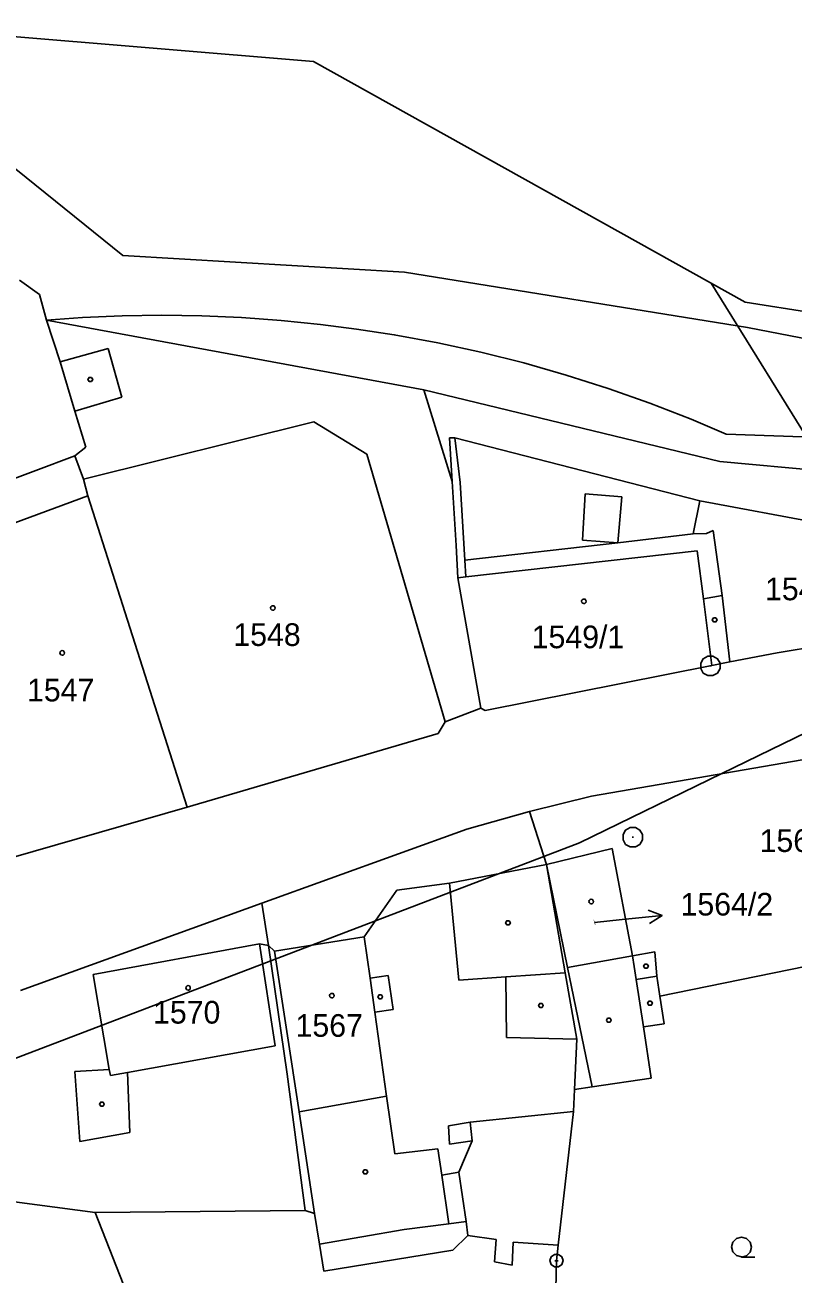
# Model space of a CAD drawing. Extents: x -806774 to -803680, y -1151731 to -1150053.
# Drawn here: x -805628.6 to -805571, y -1150573.9 to -1150480.1 of the extents above; entities that cross this region are included whole.
import ezdxf

# ---------------------------------------------------------------- set-up
doc = ezdxf.new("R2010")
doc.units = 0
for name, color, linetype in [('1', 7, 'Continuous'), ('11', 7, 'Continuous'), ('12', 7, 'Continuous'), ('2', 7, 'Continuous'), ('3', 7, 'Continuous'), ('4', 7, 'Continuous'), ('5', 7, 'Continuous'), ('6', 7, 'Continuous'), ('7', 7, 'Continuous'), ('8', 7, 'Continuous')]:
    doc.layers.add(name, color=color, linetype=linetype)

msp = doc.modelspace()

# ---------------------------------------------------------------- linework, layer by layer
at = {"layer": '1'}
for p, q in [((-805606.97, -1150482.85), (-805639.91, -1150480.12)), ((-805606.97, -1150482.85), (-805582.6, -1150496.44)), ((-805582.6, -1150496.44), (-805574.56, -1150500.92)), ((-805629.05, -1150499.28), (-805627.54, -1150500.35)), ((-805627.54, -1150500.35), (-805627.02, -1150502.26)), ((-805574.56, -1150500.92), (-805569.48, -1150501.72)), ((-805627.02, -1150502.26), (-805626, -1150505.41)), ((-805627.02, -1150502.26), (-805598.69, -1150507.5)), ((-805626, -1150505.41), (-805622.4, -1150504.41)), ((-805621.36, -1150508.04), (-805622.4, -1150504.41)), ((-805624.88, -1150509.11), (-805621.36, -1150508.04)), ((-805598.69, -1150507.5), (-805596.55, -1150514.37)), ((-805576.47, -1150512.87), (-805598.69, -1150507.5)), ((-805624.88, -1150509.11), (-805624.07, -1150511.8)), ((-805624.07, -1150511.8), (-805624.88, -1150512.45)), ((-805596.35, -1150511.09), (-805596.75, -1150511.11)), ((-805596.75, -1150511.11), (-805596.55, -1150514.37)), ((-805577.98, -1150515.83), (-805596.35, -1150511.09)), ((-805624.88, -1150512.45), (-805624.23, -1150514.21)), ((-805545.02, -1150515.82), (-805576.47, -1150512.87)), ((-805623.92, -1150515.45), (-805624.23, -1150514.21)), ((-805596.55, -1150514.37), (-805596.25, -1150519.18)), ((-805623.92, -1150515.45), (-805616.46, -1150538.83)), ((-805577.98, -1150515.83), (-805578.46, -1150518.31)), ((-805561.26, -1150518.96), (-805577.98, -1150515.83)), ((-805578.46, -1150518.31), (-805577.47, -1150518.27)), ((-805577.47, -1150518.27), (-805576.96, -1150518.06)), ((-805576.96, -1150518.06), (-805576.3, -1150522.94)), ((-805596.25, -1150519.18), (-805596.13, -1150521.6)), ((-805596.13, -1150521.6), (-805594.41, -1150531.4)), ((-805576.3, -1150522.94), (-805575.71, -1150527.92)), ((-805560.9, -1150525.36), (-805572.16, -1150527.23)), ((-805572.16, -1150527.23), (-805575.71, -1150527.92)), ((-805594.09, -1150531.56), (-805577.06, -1150528.18)), ((-805575.71, -1150527.92), (-805577.06, -1150528.18)), ((-805597.08, -1150532.42), (-805594.41, -1150531.4)), ((-805594.41, -1150531.4), (-805594.09, -1150531.56)), ((-805597.08, -1150532.42), (-805597.62, -1150533.3)), ((-805597.62, -1150533.3), (-805616.46, -1150538.83)), ((-805567, -1150534.69), (-805586.09, -1150537.99)), ((-805586.09, -1150537.99), (-805590.75, -1150539.15)), ((-805616.46, -1150538.83), (-805629.68, -1150542.61)), ((-805590.75, -1150539.15), (-805595.46, -1150540.47)), ((-805589.49, -1150543.12), (-805590.75, -1150539.15)), ((-805595.46, -1150540.47), (-805610.86, -1150546.01)), ((-805584.56, -1150541.93), (-805589.49, -1150543.12)), ((-805583.02, -1150549.97), (-805584.56, -1150541.93)), ((-805589.49, -1150543.12), (-805588.08, -1150551.24)), ((-805610.86, -1150546.01), (-805628.96, -1150552.57)), ((-805610.34, -1150549.2), (-805610.86, -1150546.01)), ((-805608.95, -1150558.85), (-805610.34, -1150549.2)), ((-805559.52, -1150548.6), (-805580.96, -1150553)), ((-805581.35, -1150549.67), (-805583.02, -1150549.97)), ((-805581.2, -1150551.5), (-805581.35, -1150549.67)), ((-805588.08, -1150551.24), (-805587.21, -1150556.23)), ((-805580.96, -1150553), (-805581.2, -1150551.5)), ((-805580.65, -1150555.07), (-805580.96, -1150553)), ((-805582.2, -1150555.31), (-805580.65, -1150555.07)), ((-805581.62, -1150559.15), (-805582.2, -1150555.31)), ((-805587.21, -1150556.23), (-805587.39, -1150560.01)), ((-805607.59, -1150569.08), (-805608.95, -1150558.85)), ((-805586.06, -1150559.81), (-805581.62, -1150559.15)), ((-805587.39, -1150560.01), (-805587.46, -1150561.66)), ((-805587.39, -1150560.01), (-805586.06, -1150559.81)), ((-805587.46, -1150561.66), (-805588.6, -1150571.69)), ((-805638.87, -1150567.2), (-805623.37, -1150569.23)), ((-805623.37, -1150569.23), (-805607.59, -1150569.08)), ((-805623.37, -1150569.23), (-805618.69, -1150581.09)), ((-805606.9, -1150569.31), (-805607.59, -1150569.08)), ((-805606.51, -1150571.62), (-805606.9, -1150569.31)), ((-805606.2, -1150573.64), (-805606.51, -1150571.62)), ((-805595.38, -1150570.95), (-805596.52, -1150572.06)), ((-805593.25, -1150571.25), (-805595.38, -1150570.95)), ((-805593.39, -1150572.95), (-805593.25, -1150571.25)), ((-805591.98, -1150571.46), (-805592.07, -1150573.19)), ((-805591.98, -1150571.46), (-805588.6, -1150571.69)), ((-805588.6, -1150571.69), (-805588.73, -1150572.86)), ((-805596.52, -1150572.06), (-805606.2, -1150573.64)), ((-805592.07, -1150573.19), (-805593.39, -1150572.95)), ((-805589.35, -1150595.34), (-805588.73, -1150572.86))]:
    msp.add_line(p, q, dxfattribs=at)
at = {"layer": '11'}
msp.add_lwpolyline([(-805774, -1150600.5), (-805744.72, -1150597.99), (-805739, -1150597.5), (-805729.96, -1150594.42), (-805690.5, -1150581), (-805687.13, -1150579.72), (-805686.21, -1150579.36), (-805662.62, -1150570.36), (-805635.57, -1150560.04), (-805633.48, -1150559.24), (-805610.18, -1150550.34), (-805589.68, -1150542.52), (-805587, -1150541.5), (-805576.31, -1150536.3), (-805549.76, -1150523.38), (-805549.38, -1150523.2), (-805535.32, -1150516.36), (-805514.906, -1150506.423)], dxfattribs=at)
at = {"layer": '12'}
for p, q in [((-805624.23, -1150514.21), (-805606.95, -1150509.89)), ((-805606.95, -1150509.89), (-805602.98, -1150512.33)), ((-805602.98, -1150512.33), (-805597.08, -1150532.42)), ((-805623.92, -1150515.45), (-805624.23, -1150514.21)), ((-805636.35, -1150520.07), (-805623.92, -1150515.45)), ((-805623.92, -1150515.45), (-805616.46, -1150538.83)), ((-805623.92, -1150515.45), (-805616.46, -1150538.83)), ((-805578.16, -1150519.57), (-805595.53, -1150521.53)), ((-805577.7, -1150523.19), (-805578.16, -1150519.57)), ((-805595.53, -1150521.53), (-805596.13, -1150521.6)), ((-805596.13, -1150521.6), (-805594.41, -1150531.4)), ((-805577.7, -1150523.19), (-805577.06, -1150528.18)), ((-805594.09, -1150531.56), (-805577.06, -1150528.18)), ((-805594.41, -1150531.4), (-805594.09, -1150531.56)), ((-805597.08, -1150532.42), (-805597.62, -1150533.3)), ((-805597.62, -1150533.3), (-805616.46, -1150538.83)), ((-805616.46, -1150538.83), (-805629.68, -1150542.61)), ((-805584.56, -1150541.93), (-805589.49, -1150543.12)), ((-805583.02, -1150549.97), (-805584.56, -1150541.93)), ((-805587.9, -1150550.85), (-805589.49, -1150543.12)), ((-805623.52, -1150551.37), (-805611.02, -1150549.07)), ((-805611.02, -1150549.07), (-805609.84, -1150556.74)), ((-805609.91, -1150549.62), (-805603.17, -1150548.54)), ((-805602.73, -1150551.65), (-805603.17, -1150548.54)), ((-805608.04, -1150561.69), (-805609.91, -1150549.62)), ((-805587.9, -1150550.85), (-805583.02, -1150549.97)), ((-805622.32, -1150558.5), (-805623.52, -1150551.37)), ((-805602.37, -1150554.2), (-805602.73, -1150551.65)), ((-805602.37, -1150554.2), (-805601.48, -1150560.51)), ((-805609.84, -1150556.74), (-805620.94, -1150558.73)), ((-805622.21, -1150558.95), (-805622.32, -1150558.5)), ((-805620.94, -1150558.73), (-805622.21, -1150558.95)), ((-805601.48, -1150560.51), (-805608.04, -1150561.69))]:
    msp.add_line(p, q, dxfattribs=at)
at = {"layer": '3'}
msp.add_lwpolyline([(-805574.83, -1150572.56), (-805575.21, -1150572.46), (-805575.48, -1150572.19), (-805575.58, -1150571.82), (-805575.48, -1150571.45), (-805575.21, -1150571.18), (-805574.84, -1150571.08), (-805574.47, -1150571.18), (-805574.2, -1150571.45), (-805574.1, -1150571.83), (-805574.2, -1150572.21), (-805574.47, -1150572.48), (-805574.85, -1150572.58), (-805573.85, -1150572.58)], dxfattribs=at)
at = {"layer": '4'}
for p, q in [((-805621.28, -1150497.43), (-805641.35, -1150481.25)), ((-805600.14, -1150498.68), (-805621.28, -1150497.43)), ((-805600.14, -1150498.68), (-805574.4, -1150502.81)), ((-805574.4, -1150502.81), (-805547.02, -1150508.22)), ((-805626, -1150505.41), (-805624.88, -1150509.11)), ((-805624.23, -1150514.21), (-805606.95, -1150509.89)), ((-805606.95, -1150509.89), (-805602.98, -1150512.33)), ((-805545.68, -1150511.92), (-805575.98, -1150510.83)), ((-805596.35, -1150511.09), (-805595.96, -1150514.45)), ((-805637.24, -1150517.09), (-805624.88, -1150512.45)), ((-805602.98, -1150512.33), (-805597.08, -1150532.42)), ((-805595.96, -1150514.45), (-805595.61, -1150520.29)), ((-805636.35, -1150520.07), (-805623.92, -1150515.45)), ((-805586.78, -1150518.78), (-805586.57, -1150515.31)), ((-805586.57, -1150515.31), (-805583.83, -1150515.54)), ((-805583.83, -1150515.54), (-805584.13, -1150518.98)), ((-805584.13, -1150518.98), (-805578.46, -1150518.31)), ((-805595.61, -1150520.29), (-805584.13, -1150518.98)), ((-805584.13, -1150518.98), (-805586.78, -1150518.78)), ((-805595.61, -1150520.29), (-805595.53, -1150521.53)), ((-805578.16, -1150519.57), (-805595.53, -1150521.53)), ((-805577.7, -1150523.19), (-805578.16, -1150519.57)), ((-805595.53, -1150521.53), (-805596.13, -1150521.6)), ((-805576.3, -1150522.94), (-805577.7, -1150523.19)), ((-805577.7, -1150523.19), (-805577.06, -1150528.18)), ((-805596.77, -1150544.52), (-805589.49, -1150543.12)), ((-805587.9, -1150550.85), (-805589.49, -1150543.12)), ((-805600.71, -1150545.04), (-805596.77, -1150544.52)), ((-805596.77, -1150544.52), (-805596.06, -1150551.79)), ((-805603.17, -1150548.54), (-805600.71, -1150545.04)), ((-805623.52, -1150551.37), (-805611.02, -1150549.07)), ((-805611.02, -1150549.07), (-805610.34, -1150549.2)), ((-805611.02, -1150549.07), (-805609.84, -1150556.74)), ((-805610.34, -1150549.2), (-805609.91, -1150549.62)), ((-805609.91, -1150549.62), (-805603.17, -1150548.54)), ((-805602.73, -1150551.65), (-805603.17, -1150548.54)), ((-805608.04, -1150561.69), (-805609.91, -1150549.62)), ((-805587.9, -1150550.85), (-805583.02, -1150549.97)), ((-805583.02, -1150549.97), (-805582.9, -1150550.78)), ((-805588.08, -1150551.24), (-805592.53, -1150551.55)), ((-805586.06, -1150559.81), (-805587.9, -1150550.85)), ((-805582.9, -1150550.78), (-805582.75, -1150551.75)), ((-805622.32, -1150558.5), (-805623.52, -1150551.37)), ((-805602.73, -1150551.65), (-805601.36, -1150551.44)), ((-805602.37, -1150554.2), (-805602.73, -1150551.65)), ((-805601.36, -1150551.44), (-805601, -1150554.01)), ((-805596.06, -1150551.79), (-805592.53, -1150551.55)), ((-805592.53, -1150551.55), (-805592.48, -1150556.11)), ((-805582.75, -1150551.75), (-805581.2, -1150551.5)), ((-805582.75, -1150551.75), (-805582.2, -1150555.31)), ((-805601, -1150554.01), (-805602.37, -1150554.2)), ((-805602.37, -1150554.2), (-805601.48, -1150560.51)), ((-805609.84, -1150556.74), (-805620.94, -1150558.73)), ((-805592.48, -1150556.11), (-805587.21, -1150556.23)), ((-805622.32, -1150558.5), (-805624.89, -1150558.65)), ((-805624.89, -1150558.65), (-805624.52, -1150563.92)), ((-805622.21, -1150558.95), (-805622.32, -1150558.5)), ((-805620.94, -1150558.73), (-805622.21, -1150558.95)), ((-805620.75, -1150563.24), (-805620.94, -1150558.73)), ((-805601.48, -1150560.51), (-805608.04, -1150561.69)), ((-805601.48, -1150560.51), (-805600.87, -1150564.84)), ((-805606.9, -1150569.31), (-805608.04, -1150561.69)), ((-805595.21, -1150562.46), (-805596.84, -1150562.73)), ((-805587.46, -1150561.66), (-805595.21, -1150562.46)), ((-805595.07, -1150563.86), (-805595.21, -1150562.46)), ((-805624.52, -1150563.92), (-805620.75, -1150563.24)), ((-805596.84, -1150562.73), (-805596.75, -1150564.1)), ((-805596.75, -1150564.1), (-805595.07, -1150563.86)), ((-805595.07, -1150563.86), (-805596.06, -1150566.22)), ((-805597.63, -1150564.46), (-805600.87, -1150564.84)), ((-805597.34, -1150566.43), (-805597.63, -1150564.46)), ((-805596.06, -1150566.22), (-805597.34, -1150566.43)), ((-805595.51, -1150569.91), (-805596.06, -1150566.22)), ((-805596.81, -1150570.08), (-805597.34, -1150566.43)), ((-805596.81, -1150570.08), (-805595.51, -1150569.91)), ((-805595.38, -1150570.95), (-805595.51, -1150569.91)), ((-805600.17, -1150570.51), (-805606.51, -1150571.62)), ((-805600.17, -1150570.51), (-805596.81, -1150570.08))]:
    msp.add_line(p, q, dxfattribs=at)
msp.add_lwpolyline([(-805627.02, -1150502.26), (-805624.318, -1150502.07), (-805621.336, -1150501.946), (-805618.351, -1150501.906), (-805615.366, -1150501.951), (-805612.384, -1150502.081), (-805609.406, -1150502.294), (-805606.436, -1150502.592), (-805603.75, -1150502.94), (-805600.909, -1150503.372), (-805597.648, -1150503.975), (-805594.407, -1150504.679), (-805591.191, -1150505.485), (-805588.001, -1150506.391), (-805584.841, -1150507.397), (-805581.714, -1150508.502), (-805578.624, -1150509.704), (-805575.98, -1150510.83)], dxfattribs=at)
at = {"layer": '5'}
for points in [[(-805623.64, -1150506.57), (-805623.55, -1150506.72), (-805623.64, -1150506.87), (-805623.82, -1150506.87), (-805623.91, -1150506.72), (-805623.82, -1150506.57)], [(-805610.03, -1150523.7), (-805609.93, -1150523.72), (-805609.88, -1150523.81), (-805609.86, -1150523.87), (-805609.88, -1150523.96), (-805609.96, -1150524.03), (-805610.03, -1150524.04), (-805610.12, -1150524.01), (-805610.18, -1150523.95), (-805610.2, -1150523.87), (-805610.18, -1150523.78), (-805610.1, -1150523.71)], [(-805586.67, -1150523.2), (-805586.57, -1150523.22), (-805586.52, -1150523.31), (-805586.5, -1150523.37), (-805586.52, -1150523.46), (-805586.6, -1150523.53), (-805586.67, -1150523.54), (-805586.76, -1150523.51), (-805586.82, -1150523.45), (-805586.84, -1150523.37), (-805586.82, -1150523.28), (-805586.74, -1150523.21)], [(-805576.76, -1150524.61), (-805576.67, -1150524.76), (-805576.76, -1150524.91), (-805576.94, -1150524.91), (-805577.03, -1150524.76), (-805576.94, -1150524.61)], [(-805625.84, -1150527.07), (-805625.74, -1150527.09), (-805625.69, -1150527.18), (-805625.67, -1150527.24), (-805625.69, -1150527.33), (-805625.77, -1150527.4), (-805625.84, -1150527.41), (-805625.93, -1150527.38), (-805625.99, -1150527.32), (-805626.01, -1150527.24), (-805625.99, -1150527.15), (-805625.91, -1150527.08)], [(-805586.12, -1150545.73), (-805586.02, -1150545.75), (-805585.97, -1150545.84), (-805585.95, -1150545.9), (-805585.97, -1150545.99), (-805586.05, -1150546.06), (-805586.12, -1150546.07), (-805586.21, -1150546.04), (-805586.27, -1150545.98), (-805586.29, -1150545.9), (-805586.27, -1150545.81), (-805586.19, -1150545.74)], [(-805592.28, -1150547.34), (-805592.19, -1150547.49), (-805592.28, -1150547.64), (-805592.46, -1150547.64), (-805592.55, -1150547.49), (-805592.46, -1150547.34)], [(-805581.92, -1150550.6), (-805581.83, -1150550.75), (-805581.92, -1150550.9), (-805582.1, -1150550.9), (-805582.19, -1150550.75), (-805582.1, -1150550.6)], [(-805616.39, -1150552.21), (-805616.29, -1150552.23), (-805616.24, -1150552.32), (-805616.22, -1150552.38), (-805616.24, -1150552.47), (-805616.32, -1150552.54), (-805616.39, -1150552.55), (-805616.48, -1150552.52), (-805616.54, -1150552.46), (-805616.56, -1150552.38), (-805616.54, -1150552.29), (-805616.46, -1150552.22)], [(-805605.59, -1150552.79), (-805605.49, -1150552.81), (-805605.44, -1150552.9), (-805605.42, -1150552.96), (-805605.44, -1150553.05), (-805605.52, -1150553.12), (-805605.59, -1150553.13), (-805605.68, -1150553.1), (-805605.74, -1150553.04), (-805605.76, -1150552.96), (-805605.74, -1150552.87), (-805605.66, -1150552.8)], [(-805601.87, -1150552.89), (-805601.78, -1150553.04), (-805601.87, -1150553.19), (-805602.05, -1150553.19), (-805602.14, -1150553.04), (-805602.05, -1150552.89)], [(-805589.81, -1150553.55), (-805589.72, -1150553.7), (-805589.81, -1150553.85), (-805589.99, -1150553.85), (-805590.08, -1150553.7), (-805589.99, -1150553.55)], [(-805581.62, -1150553.38), (-805581.53, -1150553.53), (-805581.62, -1150553.68), (-805581.8, -1150553.68), (-805581.89, -1150553.53), (-805581.8, -1150553.38)], [(-805584.71, -1150554.66), (-805584.62, -1150554.81), (-805584.71, -1150554.96), (-805584.89, -1150554.96), (-805584.98, -1150554.81), (-805584.89, -1150554.66)], [(-805622.77, -1150560.95), (-805622.68, -1150561.1), (-805622.77, -1150561.25), (-805622.95, -1150561.25), (-805623.04, -1150561.1), (-805622.95, -1150560.95)], [(-805602.99, -1150566.04), (-805602.9, -1150566.19), (-805602.99, -1150566.34), (-805603.17, -1150566.34), (-805603.26, -1150566.19), (-805603.17, -1150566.04)]]:
    msp.add_lwpolyline(points, close=True, dxfattribs=at)
at = {"layer": '6'}
msp.add_line((-805552.71, -1150538.95), (-805577.115, -1150499.496), dxfattribs=at)
at = {"layer": '7'}
for p in [(-805585.87, -1150547.48), (-805580.806, -1150546.947)]:
    msp.add_line(p, (-805583.79, -1150547.26), dxfattribs=at)
msp.add_lwpolyline([(-805581.853, -1150546.554), (-805580.806, -1150546.947), (-805581.749, -1150547.548)], dxfattribs=at)
at = {"layer": '8'}
for p, q in [((-805577.22, -1150528.21), (-805577.12, -1150528.21)), ((-805583.05, -1150541.07), (-805582.95, -1150541.07)), ((-805588.85, -1150572.86), (-805588.61, -1150572.86))]:
    msp.add_line(p, q, dxfattribs=at)
for points in [[(-805576.98, -1150527.49), (-805576.64, -1150527.68), (-805576.45, -1150528.02), (-805576.45, -1150528.41), (-805576.64, -1150528.75), (-805576.98, -1150528.94), (-805577.37, -1150528.94), (-805577.71, -1150528.75), (-805577.9, -1150528.41), (-805577.9, -1150528.02), (-805577.71, -1150527.68), (-805577.37, -1150527.49)], [(-805582.81, -1150540.35), (-805582.47, -1150540.54), (-805582.28, -1150540.88), (-805582.28, -1150541.27), (-805582.47, -1150541.61), (-805582.81, -1150541.8), (-805583.2, -1150541.8), (-805583.54, -1150541.61), (-805583.73, -1150541.27), (-805583.73, -1150540.88), (-805583.54, -1150540.54), (-805583.2, -1150540.35)], [(-805588.58, -1150572.38), (-805588.33, -1150572.56), (-805588.23, -1150572.85), (-805588.33, -1150573.14), (-805588.58, -1150573.32), (-805588.89, -1150573.32), (-805589.14, -1150573.14), (-805589.24, -1150572.85), (-805589.14, -1150572.56), (-805588.89, -1150572.38)]]:
    msp.add_lwpolyline(points, close=True, dxfattribs=at)

# ---------------------------------------------------------------- texts
at = {"layer": '2'}
for s, p in [('1549/2', (-805573.075, -1150523.29)), ('1548', (-805612.992, -1150526.72)), ('1549/1', (-805590.593, -1150526.89)), ('1547', (-805628.482, -1150530.88)), ('1564/1', (-805573.483, -1150542.18)), ('1570', (-805619.019, -1150555.06)), ('1567', (-805608.322, -1150556.05))]:
    msp.add_text(s, height=1.7, dxfattribs=at).set_placement(p)
msp.add_text('1564/2', height=0.1, rotation=278.97315, dxfattribs=at).set_placement((-805585.955, -1150547.261))
at = {"layer": '7'}
msp.add_text('1564/2', height=1.7, dxfattribs=at).set_placement((-805579.417, -1150546.95))

doc.saveas('drawing.dxf')
